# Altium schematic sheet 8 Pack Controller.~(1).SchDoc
size A
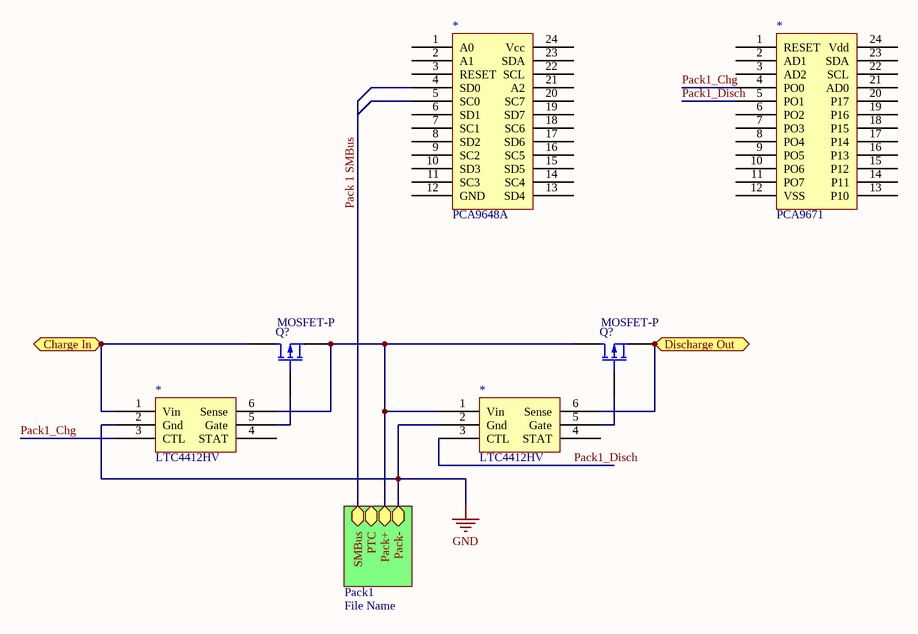
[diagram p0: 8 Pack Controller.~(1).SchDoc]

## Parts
(Parts that share a designator on the sheet are numbered #1, #2 ... from top to bottom, then left to right.)
*#1  PCA9648A
*#2  PCA9671
*#3  LTC4412HV
*#4  LTC4412HV
Q?#1  MOSFET-P  [BCY-W3/B.8]
Q?#2  MOSFET-P  [BCY-W3/B.8]

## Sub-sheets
Pack1 = File Name: SMBus, PTC, Pack+, Pack-

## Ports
Charge In, Discharge Out

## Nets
GND: *#3.2(Gnd) *#4.2(Gnd) ; sheet Pack1/Pack-
Charge In: *#3.1(Vin) Q?#1.1(D) ; port Charge In
Discharge Out: *#4.6(Sense) Q?#2.3(S) ; port Discharge Out
Pack1_Chg: *#2.4(PO0) *#3.3(CTL)
Pack1_Disch: *#2.5(PO1) *#4.3(CTL)
Net*#3_5: *#3.5(Gate) Q?#1.2(G)
Net*#3_6: *#3.6(Sense) *#4.1(Vin) Q?#1.3(S) Q?#2.1(D) ; sheet Pack1/Pack+
Net*#4_5: *#4.5(Gate) Q?#2.2(G)

Not connected (* = marked no-connect by the designer): *#1 1(A0) 2(A1) 3(RESET) 4(SD0) 5(SC0) 6(SD1) 7(SC1) 8(SD2) 9(SC2) 10(SD3) 11(SC3) 12(GND) 13(SD4) 14(SC4) 15(SD5) 16(SC5) 17(SD6) 18(SC6) 19(SD7) 20(SC7) 21(A2) 22(SCL) 23(SDA) 24(Vcc); *#2 1(RESET) 2(AD1) 3(AD2) 6(PO2) 7(PO3) 8(PO4) 9(PO5) 10(PO6) 11(PO7) 12(VSS) 13(P10) 14(P11) 15(P12) 16(P13) 17(P14) 18(P15) 19(P16) 20(P17) 21(AD0) 22(SCL) 23(SDA) 24(Vdd); *#3 4(STAT); *#4 4(STAT)

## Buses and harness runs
bus Pack 1 SMBus = sheet Pack1/SMBus

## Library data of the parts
Q?#1 Q?#2 = MOSFET-P: P-Channel MOSFET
